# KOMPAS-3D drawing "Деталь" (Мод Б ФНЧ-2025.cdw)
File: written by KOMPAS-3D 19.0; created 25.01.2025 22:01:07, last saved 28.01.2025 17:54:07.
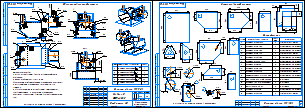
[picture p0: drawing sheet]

Sheets 1-2: A3, landscape

Document properties: Автор: Степан; Масса: 7.18131; Форматы листов документа: 2xA3; Полное имя файла: C:\Users\WELDER_72\OneDrive\Desktop\ггавп\КОМПАС 3Д\Мод Б ФНЧ-2025.cdw

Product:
- Part/product: Деталь
    Масса: 7.18131
  - Body: Тело 30
      Масса: 0.068488
  - Body: Тело 1
      Масса: 1.47693
  - Body: Тело 2
      Масса: 1.22499
  - Body: Тело 3
      Масса: 1.23504
  - Body: Тело 4
      Масса: 0.768467
  - Body: Тело 9
      Масса: 0.207398
  - Body: Тело 10
      Масса: 0.185121
  - Body: Тело 11
      Масса: 1.23504
  - Body: Тело 13
      Масса: 0.185121
  - Body: Тело 14
      Масса: 0.655909
  - Body: Тело 15
      Масса: 0.159935
  - Body: Тело 20
      Масса: 0.282841
  - Body: Тело 21
      Масса: 0.0823223
  - Body: Тело 24
      Масса: 0.420327
  - Body: Тело 25
      Масса: 0.068488
  - Body: Тело 26
      Масса: 0.159935

Title block, sheet 1: Наименование: Модуль Б / ФНЧ-2025; designation: Процесс сварки 111 (РД); Материал: Ст3, сталь 20; Масса: 7,18; sheet number: 1; Количество листов документа: 2; organisation: Чемпионат ПМ / "Профессионалы"; Форматы листов документа: A3; stored path: C:\Users\Степан\Desktop\Модуль Ж Степана.cdw; Разработал: Степанов С.С.; Проверил: Калашников В.А.; Утвердил: Дюкова С. В.
Title block, sheet 2: sheet number: 2

Views: Вид А, Спереди 1, Спереди, Проекционный вид 2, Проекционный вид 3, Проекционный вид 7
Referenced files in C:\Users\Степан\Desktop\Модули на РЧ\: Мод Б РЧ Степана.m3d
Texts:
  Технические условия:
  1. Сборка производится в любом пространственном
  положении;
  2. Длина прихваток не более 10 мм.
  Располагать прихватки внутри конструкции запрещено;
  3. Предоставить конструкцию для контроля без
  детали "8".
  4. Сварка конструкции производится относительно
  базовой пластины "1", наклонять конструкцию
  запрещено, допускается вращать вокруг вертикальной
  оси;
  Все расмеры на чертеже указаны в миллиметрах
  № шва
  Стандарт и обозначение
  Кол-во
  ГОСТ 5264-800-Т1- 4 +2
  ГОСТ 23518-79-У1- 4 +6
  ГОСТ 23518-79-Т5- 4 +2
  ГОСТ 5264-800-У4- 4 +2
  ГОСТ 5264-800-С2
  № дет.
  Наименование, размеры
  шт.
  Пластина 4х235х200
  Прямоугольная форма
  Пластина 4х130х172
  Сложная форма, см. чертеж
  Пластина 4х152х88
  Пластина 4х149х152
  Пластина 4х77,88х77,8
  Пластина 4х135х55
  Пластина 4х152х172
  Пластина 4х120х75
  Пластина 4х135х60 с рад.  67,5 мм
  Труба  88,5х4 - 80 с отв.  21,5 мм
  См. чертеж
  Пластина  80,5х4 (заглушка)
  Труба  21.,5х2,8 - 50
  Пластина 4х65х152
  Пластина 4х120х55
  Сборочно-сварочный чертеж
  Деталировочный чертеж
Dimensions and other numbers on the sheet: 2; 5; 7; 11; 12; 13; 44 2; 35 2; 97; 65; 152; 10; 19 2; 1; 6; 8; 9; 3; 4; 18; 235; 200; 107; 130; 172; 117; 55; 88; 77,8; 135; 84; 120; 75; 88,5; 80; 30; 21,5; 80,5; 1/2"; 14; 15; 16; 19; 70; 45; 41; 50 2; 60; 67,5; 37,5; 23 2; 61 2; 12 2; 16 2; 20 2; 1:3; 7,18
